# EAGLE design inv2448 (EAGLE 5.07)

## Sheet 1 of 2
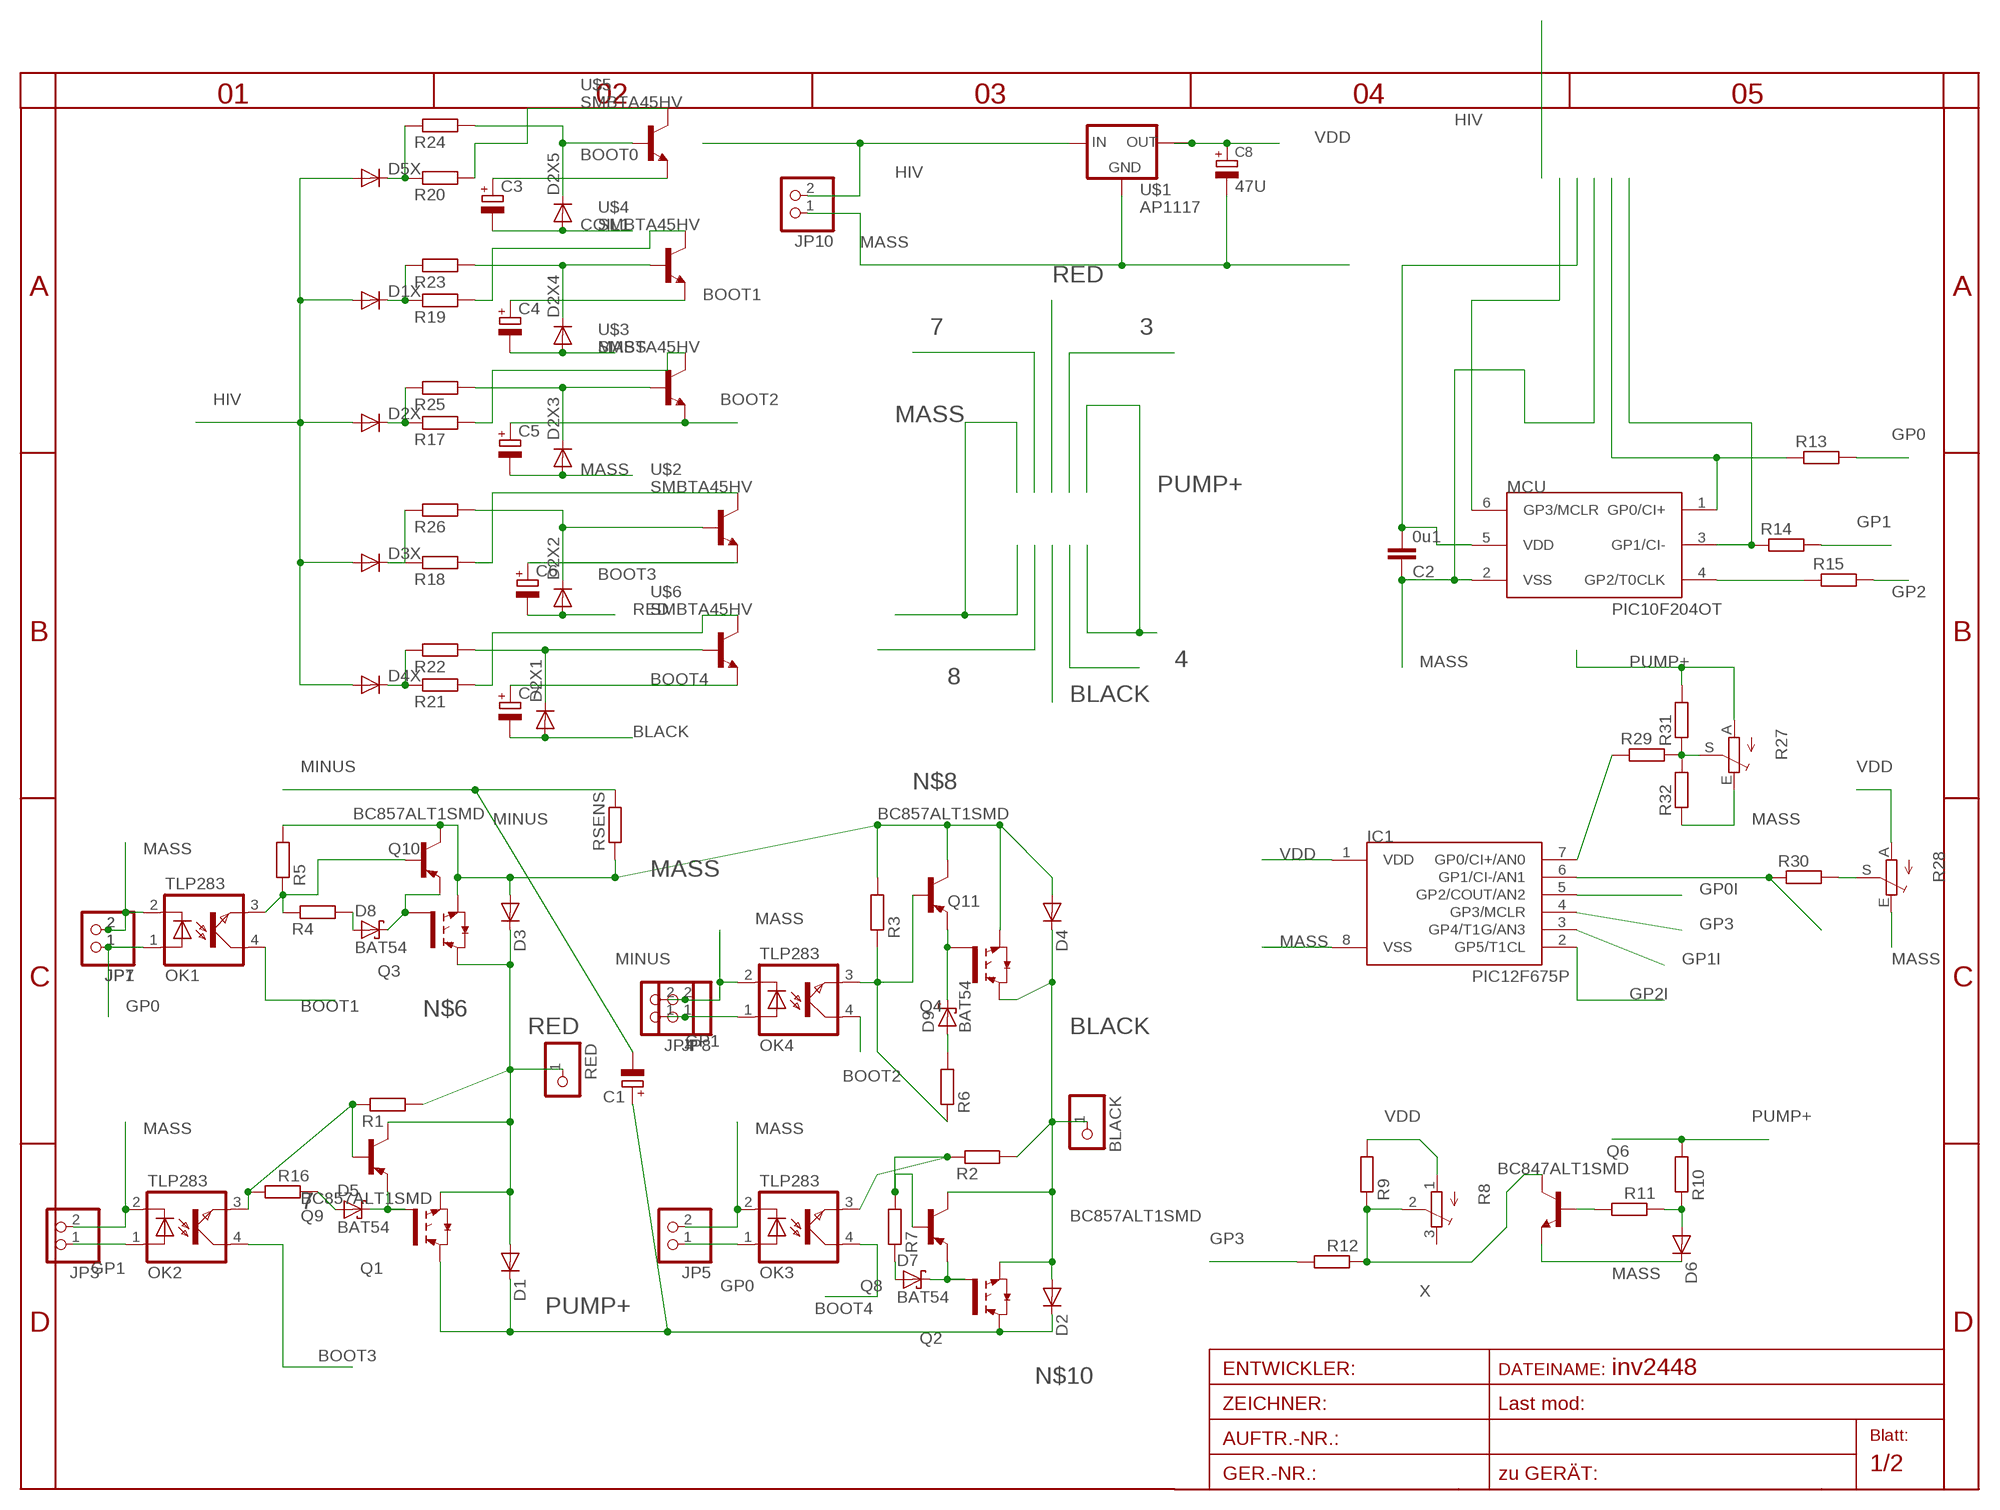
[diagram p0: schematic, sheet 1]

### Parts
BLACK  PINHD-1X14.5MM  [1X4MM5]
C1  CPOL-EUE5-13  [E5-13]
C2  0u1  C-EUC0805  [C0805]
C3  CPOL-EUC  [PANASONIC_C]
C4  CPOL-EUC  [PANASONIC_C]
C5  CPOL-EUC  [PANASONIC_C]
C6  CPOL-EUC  [PANASONIC_C]
C7  CPOL-EUC  [PANASONIC_C]
C8  47U  CPOL-EUC  [PANASONIC_C]
D1  DIODE-SMC  [SMC]
D1X  DIODE-SMA-DO214  [SMA-DO214AC]
D2  DIODE-SMC  [SMC]
D2X  DIODE-SMA-DO214  [SMA-DO214AC]
D2X1  DIODE-MINIMELF  [MINIMELF]
D2X2  DIODE-MINIMELF  [MINIMELF]
D2X3  DIODE-MINIMELF  [MINIMELF]
D2X4  DIODE-MINIMELF  [MINIMELF]
D2X5  DIODE-MINIMELF  [MINIMELF]
D3  DIODE-SMC  [SMC]
D3X  DIODE-SMA-DO214  [SMA-DO214AC]
D4  DIODE-SMC  [SMC]
D4X  DIODE-SMA-DO214  [SMA-DO214AC]
D5  BAT54  [SOT23]
D5X  DIODE-SMA-DO214  [SMA-DO214AC]
D6  DIODE-MINIMELF  [MINIMELF]
D7  BAT54  [SOT23]
D8  BAT54  [SOT23]
D9  BAT54  [SOT23]
IC1  PIC12F675P  [DIL8]
JP1  PINHD-1X2STR  [1X02]
JP3  PINHD-1X2STR  [1X02]
JP4  PINHD-1X2STR  [1X02]
JP5  PINHD-1X2STR  [1X02]
JP7  PINHD-1X2STR  [1X02]
JP8  PINHD-1X2STR  [1X02]
JP10  PINHD-1X2STR  [1X02]
MCU  PIC10F204OT  [SOT23-6]
OK1  TLP283  [MINI-FLAT-4]
OK2  TLP283  [MINI-FLAT-4]
OK3  TLP283  [MINI-FLAT-4]
OK4  TLP283  [MINI-FLAT-4]
Q1  IRG4BC15UD-S  [D2PACK]
Q2  IRG4BC15UD-S  [D2PACK]
Q3  IRG4BC15UD-S  [D2PACK]
Q4  IRG4BC15UD-S  [D2PACK]
Q6  BC847ALT1SMD  [SOT23]
Q8  BC857ALT1SMD  [SOT23-BEC]
Q9  BC857ALT1SMD  [SOT23-BEC]
Q10  BC857ALT1SMD  [SOT23-BEC]
Q11  BC857ALT1SMD  [SOT23-BEC]
R1  R-EU_R1206  [R1206]
R2  R-EU_R1206  [R1206]
R3  R-EU_R1206  [R1206]
R4  R-EU_R1206  [R1206]
R5  R-EU_R1206  [R1206]
R6  R-EU_R1206  [R1206]
R7  R-EU_R1206  [R1206]
R8  TRIM_EU-3223W  [3223W]
R9  R-EU_R1206  [R1206]
R10  R-EU_R1206  [R1206]
R11  R-EU_R1206  [R1206]
R12  R-EU_0204/7  [0204/7]
R13  R-EU_R0805  [R0805]
R14  R-EU_0207/10  [0207/10]
R15  R-EU_0207/20  [0207/20]
R16  R-EU_R1206  [R1206]
R17  R-EU_R1206  [R1206]
R18  R-EU_R1206  [R1206]
R19  R-EU_R1206  [R1206]
R20  R-EU_R1206  [R1206]
R21  R-EU_R1206  [R1206]
R22  R-EU_R1206  [R1206]
R23  R-EU_R1206  [R1206]
R24  R-EU_R1206  [R1206]
R25  R-EU_R1206  [R1206]
R26  R-EU_R1206  [R1206]
R27  TRIM_EU-RAND160  [RANDL]
R28  TRIM_EU-RAND160  [RANDL]
R29  R-EU_0207/30  [0207/30]
R30  R-EU_R0805  [R0805]
R31  R-EU_0207/30  [0207/30]
R32  R-EU_R0805  [R0805]
RED  PINHD-1X14.5MM  [1X4MM5]
RSENS  R-EU_CERAM50  [CERAM50]
U$1  AP1117  [SOT223]
U$2  SMBTA45HV  [SOT23HV]
U$3  SMBTA45HV  [SOT23HV]
U$4  SMBTA45HV  [SOT23HV]
U$5  SMBTA45HV  [SOT23HV]
U$6  SMBTA45HV  [SOT23HV]

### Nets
3: OK1.3(EMIT) Q10.B R4.1 R5.1
4: OK3.3(EMIT) Q8.B R2.1 R7.2
7: OK2.3(EMIT) Q9.B R1.1 R16.2
BLACK: BLACK.1 C7.- D2.A D2X1.A D4.C Q2.3(E) Q4.2(C) Q8.C R2.2
BOOT0: C3.+ U$5.2(E) ; also sheet 2
BOOT1: C4.+ OK1.4(COL) U$4.2(E)
BOOT2: C5.+ OK4.4(COL) U$3.2(E)
BOOT3: C6.+ OK2.4(COL) U$2.2(E)
BOOT4: C7.+ OK3.4(COL) U$6.2(E)
COIL1: C3.- D2X5.A ; also sheet 2
GP0: JP1.1 JP5.1 JP7.1 OK1.1(A) OK3.1(A) R13.2
GP0I: IC1.5(GP2/COUT/AN2) MCU.1(GP0/CI+) R13.1
GP1: JP3.1 JP4.1 JP8.1 OK2.1(A) OK4.1(A) R14.2
GP1I: IC1.3(GP4/T1G/AN3) MCU.3(GP1/CI-) R14.1
GP2: R15.2 ; also sheet 2
GP2I: IC1.2(GP5/T1CL) MCU.4(GP2/T0CLK) R15.1
GP3: IC1.4(GP3/MCLR) MCU.6(GP3/MCLR) R12.2
HIV: D1X.A D2X.A D3X.A D4X.A D5X.A JP10.2 U$1.3(IN) ; also sheet 2
MASS: C2.1 C4.- C5.- C8.- D2X3.A D2X4.A D3.A D4.A D6.C IC1.8(VSS) JP1.2 JP3.2 JP4.2 JP5.2 JP7.2 JP8.2 JP10.1 MCU.2(VSS) OK1.2(C) OK2.2(C) OK3.2(C) OK4.2(C) Q3.3(E) Q4.3(E) Q6.2(E) Q10.C Q11.C R3.2 R5.2 R27.E R28.E R32.1 RSENS.1 U$1.1(GND) ; also sheet 2
MINUS: C1.- RSENS.2 ; also sheet 2
N$2: D8.1(A) R4.2
N$4: D6.A R10.1 R11.1
N$5: Q6.1(B) R11.2
N$6: D8.3(C) Q3.1(G) Q10.E
N$7: D9.3(C) Q4.1(G) Q11.E
N$8: OK4.3(EMIT) Q11.B R3.1 R6.1
N$9: D9.1(A) R6.2
N$10: D7.3(C) Q2.1(G) Q8.E
N$11: D7.1(A) R7.1
N$12: D5.1(A) R16.1
N$13: D3X.K(C) R18.1 R26.1
N$14: D5.3(C) Q1.1(G) Q9.E
N$15: D4X.K(C) R21.1 R22.1
N$16: D2X.K(C) R17.1 R25.1
N$17: D1X.K(C) R19.1 R23.1
N$18: D5X.K(C) R20.1 R24.1
N$19: D2X1.C R22.2 U$6.1(B)
N$20: D2X5.C R24.2 U$5.1(B)
N$21: D2X4.C R23.2 U$4.1(B)
N$22: D2X2.C R26.2 U$2.1(B)
N$23: D2X3.C R25.2 U$3.1(B)
N$24: R28.S R30.2
N$25: R18.2 U$2.3(C)
N$26: R21.2 U$6.3(C)
N$27: R17.2 U$3.3(C)
N$28: R20.2 U$5.3(C)
N$29: R19.2 U$4.3(C)
N$31: IC1.6(GP1/CI-/AN1) R30.1
N$34: R27.S R29.2 R31.1 R32.2
N$35: IC1.7(GP0/CI+/AN0) R29.1
PUMP+: C1.+ D1.C D2.C Q1.2(C) Q2.2(C) R10.2 R27.A R31.2 ; also sheet 2
RED: C6.- D1.A D2X2.A D3.C Q1.3(E) Q3.2(C) Q9.C R1.2 RED.1
VDD: C2.2 C8.+ IC1.1(VDD) MCU.5(VDD) R8.1(A) R9.2 R28.A U$1.2(OUT) U$1.4(TAB)
X: Q6.3(C) R8.2(S) R9.1 R12.1
Unconnected: R8.3(E)

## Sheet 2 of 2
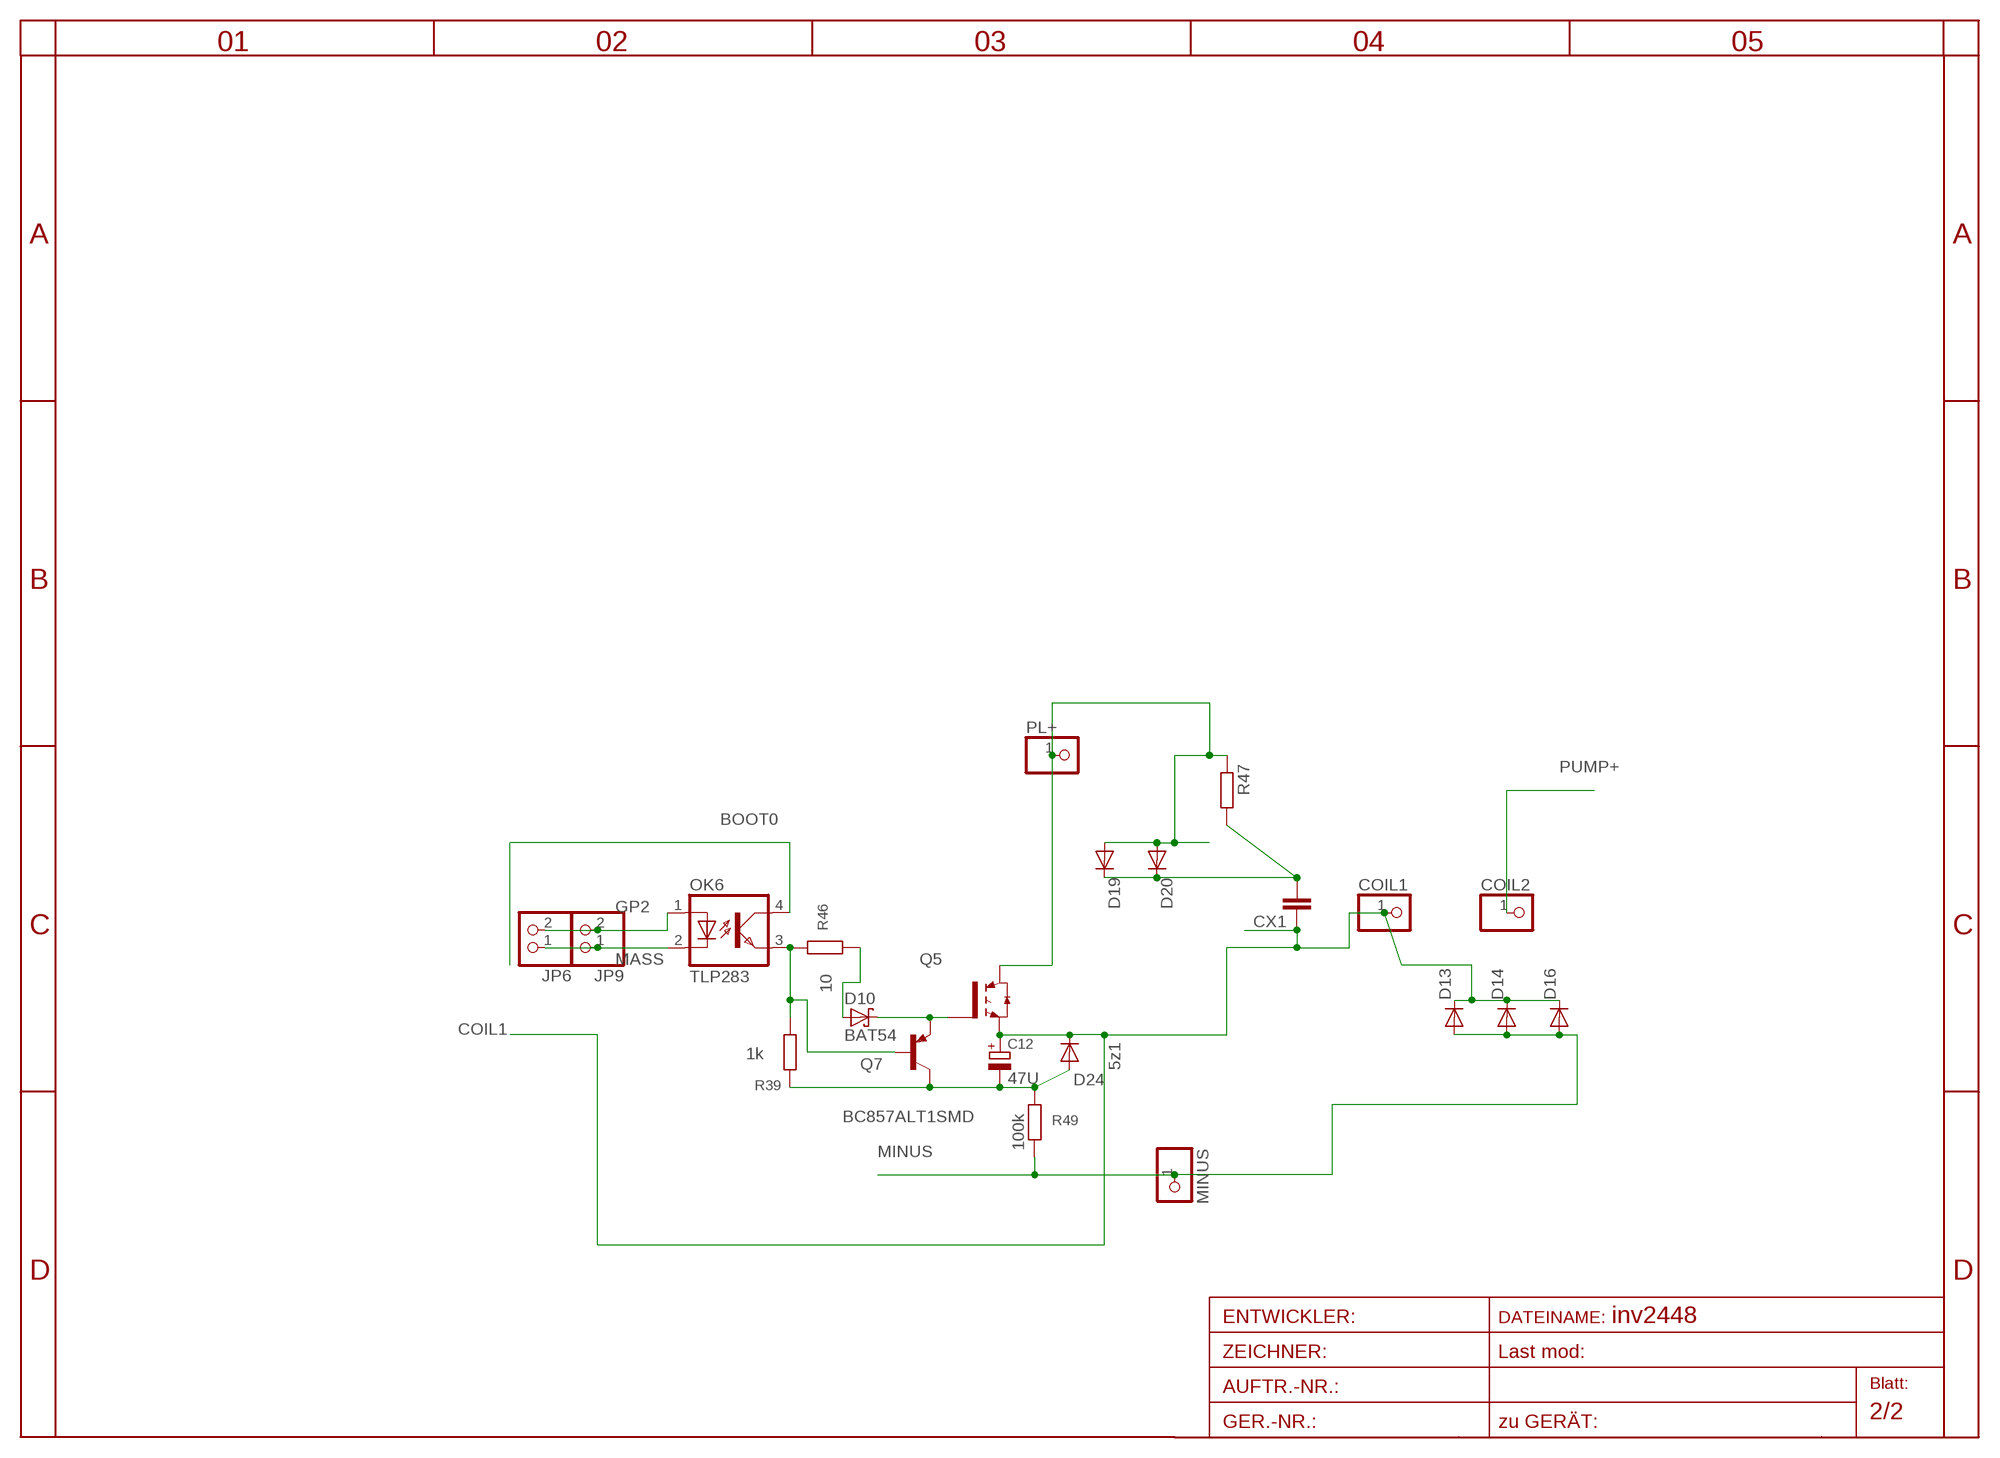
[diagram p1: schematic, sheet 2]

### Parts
C12  47U  CPOL-EUC  [PANASONIC_C]
COIL1  PINHD-1X14.5MM  [1X4MM5]
COIL2  PINHD-1X14.5MM  [1X4MM5]
CX1  CXXC22B10  [XC22B10]
D10  BAT54  [SOT23]
D13  DIODE-SMC  [SMC]
D14  DIODE-SMC  [SMC]
D16  DIODE-SMC  [SMC]
D19  DIODE-SMC  [SMC]
D20  DIODE-SMC  [SMC]
D24  5z1  DIODE-MINIMELF  [MINIMELF]
JP6  PINHD-1X2STR  [1X02]
JP9  PINHD-1X2STR  [1X02]
MINUS  PINHD-1X14.5MM  [1X4MM5]
OK6  TLP283  [MINI-FLAT-4]
PL+  PINHD-1X14.5MM  [1X4MM5]
Q5  IRG4BC15UD-S  [D2PACK]
Q7  BC857ALT1SMD  [SOT23-BEC]
R39  1k  R-EU_R1206  [R1206]
R46  10  R-EU_R1206  [R1206]
R47  R-EU_0207/5V  [0207/5V]
R49  100k  R-EU_R1206  [R1206]

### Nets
BATT-: C12.- D24.A Q7.C R39.1 R49.2
BOOT0: OK6.4(COL) ; also sheet 1
COIL1: C12.+ COIL1.1 CX1.1 D13.C D14.C D16.C D24.C Q5.3(E) ; also sheet 1
GP2: JP6.2 JP9.2 OK6.1(A) ; also sheet 1
HIV: D19.A D20.A PL+.1 Q5.2(C) R47.1 ; also sheet 1
MASS: JP6.1 JP9.1 OK6.2(C) ; also sheet 1
MINUS: D13.A D14.A D16.A MINUS.1 R49.1 ; also sheet 1
N$1: D10.3(C) Q5.1(G) Q7.E
N$3: D10.1(A) R46.1
N$43: OK6.3(EMIT) Q7.B R39.2 R46.2
PUMP+: COIL2.1 ; also sheet 1
SNUB: CX1.2 D19.C D20.C R47.2

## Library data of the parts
BLACK COIL1 COIL2 MINUS PL+ RED = pinhead:PINHD-1X1: PIN HEADER
C1 C3-C7 = rcl:CPOL-EU: POLARIZED CAPACITOR, European symbol
C2 = rcl:C-EU: CAPACITOR, European symbol
C8 C12 = rcl-2:CPOL-EU: POLARIZED CAPACITOR, European symbol
CX1 = rcl:CX: X CAPACITOR
D1 D1X D2 D2X D2X1-D2X5 D3 D3X D4 D4X D5X D6 D13 D14 D16 D19 D20 D24 = diode:DIODE-: DIODE
D5 D7-D10 = diode:BAT54: Schottky Diodes
IC1 = microchip-5:PIC12F6*: uPC nW 1k Program Flash memory 2x Timer Comparator 10b A/D converter/ 4xIN
JP1 JP3-JP10 = pinhead:PINHD-1X2: PIN HEADER
MCU = microchip-3:PIC10F2*: uPC nW 0,25/0,5k Program Flash memory Comparator
OK1-OK4 OK6 = optocoupler:TLP283: TOSHIBA PHOTOCOUPLER GaAs IRED & PHOTO-TRANSISTOR Source: http://www.semicon.toshiba.co.jp/td/en/Opto/Photocoupler/en_20050928_TLP283_datasheet.pdf
Q1-Q5 = transistor-power:IRG4BC15UD-: INSULATED GATE BIPOLAR TRANSISTOR WITH ULTRAFAST SOFT RECOVERY DIODE
Q6 = transistor-npn:BC847*: NPN Transistor
Q7-Q11 = transistor-pnp:BC857*: PNP Transistror
R1-R7 R9-R12 R16-R26 R47 RSENS = rcl:R-EU_: RESISTOR, European symbol
R8 R27 R28 = pot:TRIM_EU-: POTENTIOMETER
R13-R15 R29-R32 R39 R46 R49 = rcl-2:R-EU_: RESISTOR, European symbol
U$1 = v-reg:AP1117
U$2-U$6 = transistor-npn:SMBTA45

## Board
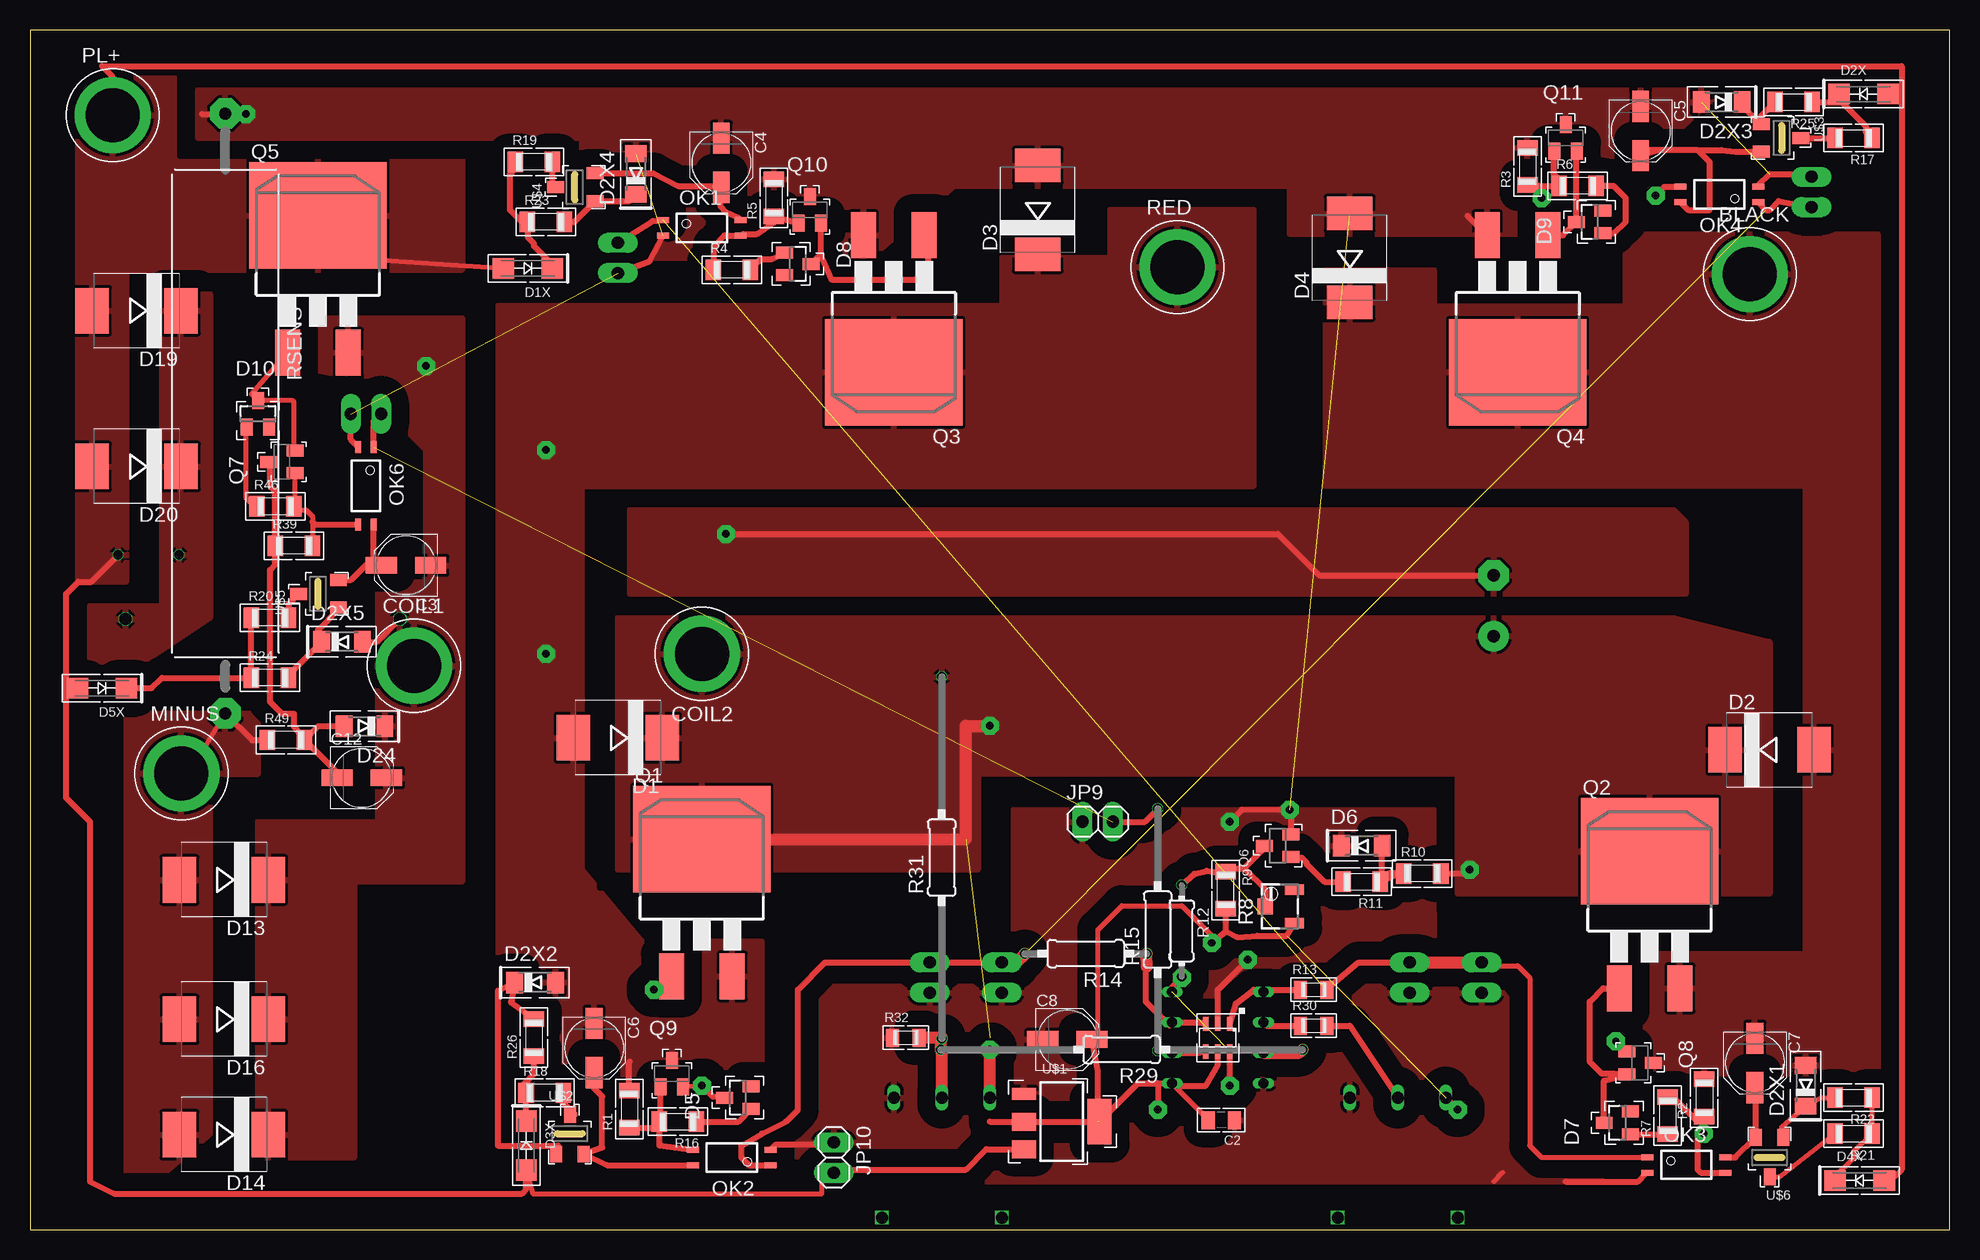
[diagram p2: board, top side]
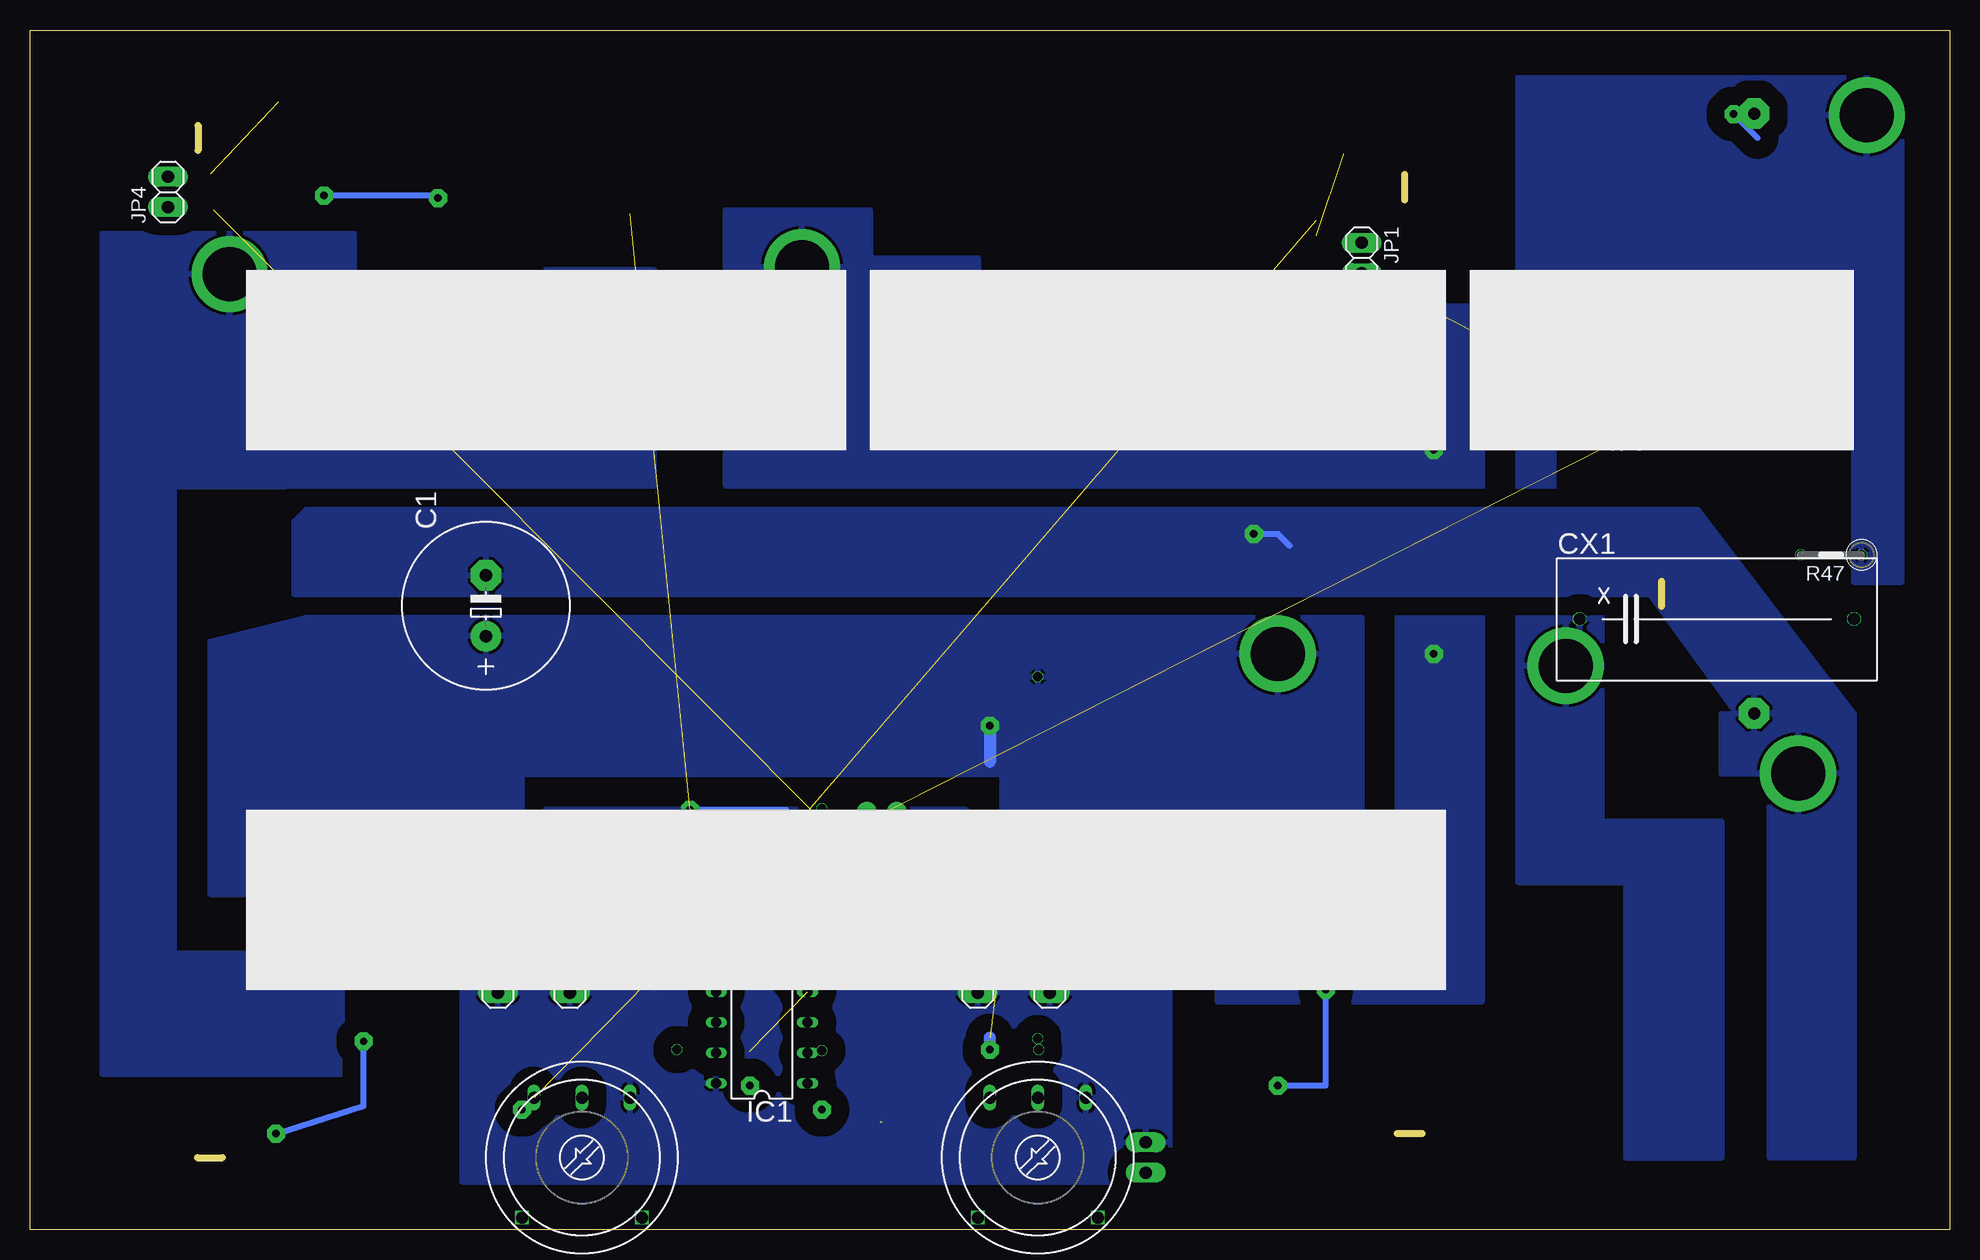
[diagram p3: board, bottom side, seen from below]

Size 160 x 100 mm. Coordinates in mm from the lower left corner, seen from the top.
Outline: 0,0 160,0 160,100 0,100 0,0
Copper layers (1*16): Top 0.035mm / dielectric 1.5mm / Bottom 0.035mm
Design rules "default": minimum track width 10mil, minimum drill 20mil, track to track 8mil, track to pad 8mil, pad to pad 8mil, via to via 8mil, smd to smd 8mil, copper to edge 40mil, drill to drill 8mil, minimum pad ring 1mil, minimum via ring 8mil, stop-mask expansion 4mil, vias tented up to drill 0mil, thermal gap 10mil

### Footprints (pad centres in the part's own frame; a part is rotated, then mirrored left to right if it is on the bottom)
1X4MM5 = drill 4.5 pad 6.35 round: 1 0,0
E5-13 = drill 1.016 pad 2.54 round: + -2.54,0 | drill 1.016 pad 2.54 octagon: - 2.54,0
C0805 = smd 1.1 x 1.5: 1 -1.1,0; 2 1.1,0
PANASONIC_C = smd 2.6 x 1.4: + 2.05,0; - -2.05,0
XC22B10 = drill 1.016 octagon: 1 -11.43,0.025; 2 11.43,0.025
SMC = smd 2.8 x 3.8: A 3.7,0; C -3.7,0
SMA-DO214AC = smd 1.8 x 1.7: A 2.05,-0.127; K -2.05,-0.127
MINIMELF = smd 1.4 x 1.8: A 1.7,0; C -1.7,0
SOT23 = smd 1 x 1.4: 1 -0.95,-1.1; 2 0.95,-1.1; 3 0,1.1
DIL8 = drill 0.8 long: 1 -3.81,-3.81; 2 -1.27,-3.81; 3 1.27,-3.81; 4 3.81,-3.81; 5 3.81,3.81; 6 1.27,3.81; 7 -1.27,3.81; 8 -3.81,3.81
1X02 = drill 1.016 pad 1.676 long: 1 -1.27,0; 2 1.27,0
SOT23-6 = smd 0.45 x 1.2: 1 -1.016,-1.15; 2 0,-1.15; 3 1.016,-1.15; 4 1.016,1.15; 5 0,1.15; 6 -1.016,1.15
MINI-FLAT-4 = smd 1 x 0.5: 1 -3.24,0.635; 2 -3.24,-0.635; 3 3.24,-0.635; 4 3.24,0.635
D2PACK = smd 2.083 x 3.81: 1 -2.54,-8.89; 3 2.54,-8.89 | smd 11.43 x 8.89: 2 0,2.54
SOT23-BEC = smd 1 x 1.4: B -0.95,-1.1; C 0,1.1; E 0.95,-1.1
R1206 = smd 1.3 x 1.7: 1 -1.55,0; 2 1.55,0
3223W = smd 0.9 x 1.6: 1 -1.4,-1.215; 3 1.4,-1.215 | smd 1.3 x 1.3: 2 0,1.215
0204/7 = drill 0.813 octagon: 1 -3.81,0; 2 3.81,0
R0805 = smd 1.1 x 1.5: 1 -1.1,0; 2 1.1,0
0207/10 = drill 0.813 octagon: 1 -5.08,0; 2 5.08,0
0207/20 = drill 0.813 octagon: 1 -10.08,0; 2 10.08,0
RANDL = drill 1 long: A -4,5; E 4,5; S 0,5 | drill 1 square: P$1 -5,-5; P$2 5,-5
0207/30 = drill 0.813 octagon: 1 -15.08,0; 2 15.08,0
0207/5V = drill 0.813 octagon: 1 -2.54,0; 2 2.54,0
CERAM50 = drill 1 pad 2.54 octagon: 1 -25,0; 2 25,0
SOT223 = smd 1 x 2: 1 -2.3,-3.15 | smd 1.5 x 2: 2 0,-3.15; 3 2.3,-3.15 | smd 3.8 x 2: 4 0,3.15
SOT23HV = smd 1 x 1.4: 1 -1.15,-1.7; 2 1.15,-1.7; 3 0,1.6

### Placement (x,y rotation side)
BLACK  143.35,79.64 0 top
C1  122,52 90 bottom
C2  99.3,9.12 180 top
C3  31.34,55.37 180 top
C4  57.62,88.92 270 top
C5  134.25,91.57 270 top
C6  47.02,15.13 270 top
C7  143.78,13.89 270 top
C8  86.46,15.85 0 top
C12  27.65,37.66 0 top
COIL1  32,47 0 top
COIL2  56,48 180 top
CX1  19.39,50.87 0 bottom
D1  49,41 180 top
D1X  41.5,80 180 top
D2  145,40 0 top
D2X  152.83,94.78 0 top
D2X1  148,12 90 top
D2X2  42.1,20.6 0 top
D2X3  141,94 180 top
D2X4  50.5,88 90 top
D2X5  26,49 0 top
D3  84,85 90 top
D3X  41.5,7 270 top
D4  110,81 90 top
D4X  152.51,4.22 0 top
D5  59,11 90 top
D5X  6,45 180 top
D6  111,32 0 top
D7  132.3,8.9 90 top
D8  64,80.5 270 top
D9  130,84 90 top
D10  19,68 0 top
D13  16.16,29.15 180 top
D14  16.16,7.91 180 top
D16  16.16,17.53 180 top
D19  8.88,76.59 180 top
D20  8.88,63.62 180 top
D24  27.89,41.96 180 top
IC1  99,16 90 bottom
JP1  49,81 270 bottom
JP3  75,21 270 bottom
JP4  148.5,86.5 90 bottom
JP5  121,21 270 bottom
JP6  28,68 180 bottom
JP7  115,21 270 bottom
JP8  81,21 270 bottom
JP9  89,34 0 top
JP10  67,6 270 top
MCU  99,16 180 top
MINUS  12.62,38.02 0 top
OK1  56,83.5 0 top
OK2  58.5,6 180 top
OK3  138.06,5.38 0 top
OK4  140.81,86.29 180 top
OK6  28,62 270 top
PL+  6.89,92.9 0 top
Q1  56,30 0 top
Q2  135,29 0 top
Q3  72,74 180 top
Q4  124,74 180 top
Q5  24,82 0 top
Q6  104,32 90 top
Q7  21,64 90 top
Q8  134.2,13.9 270 top
Q9  53.5,13 0 top
Q10  65,85 0 top
Q11  128,91 0 top
R1  49.95,10.05 90 top
R2  139.55,10.98 90 top
R3  124.83,88.62 90 top
R4  58.5,80 0 top
R5  62,86 90 top
R6  129,87 0 top
R7  136.5,9.5 90 top
R8  104.18,26.94 90 top
R9  99.67,28.3 270 top
R10  116.05,29.67 0 top
R11  111,29 180 top
R12  96,24.9 270 top
R13  107,20 0 top
R14  88,23 180 top
R15  94,25 90 top
R16  54,9 180 top
R17  152,91 180 top
R18  42.9,11.4 0 top
R19  42,89 0 top
R20  20,51 0 top
R21  152,8 180 top
R22  152,11 180 top
R23  43,84 0 top
R24  20,46 0 top
R25  147,94 180 top
R26  42,16 90 top
R27  76,6 0 bottom
R28  114,6 0 bottom
R29  91,15 180 top
R30  107,17 0 top
R31  76,31 90 top
R32  73,16 0 top
R39  22,57 0 top
R46  20.46,60.28 0 top
R47  9.88,56.24 180 bottom
R49  21.34,40.81 0 top
RED  95.65,80.23 0 top
RSENS  16.29,68.04 270 top
U$1  86,9 270 top
U$2  45,8 0 top
U$3  146,91 270 top
U$4  45.4,86.9 90 top
U$5  24,53 90 top
U$6  145,6 180 top

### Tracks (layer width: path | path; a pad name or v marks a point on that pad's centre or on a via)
3
  Top 0.5: Q10.B 62.05,84.45 R5.1 62,84 60.6,83 59.48,83 OK1.3 57.87,82.86 57,82 57,80.05 R4.1
4  (via drill 0.6 pad 1.5)
  Top 0.5: Q8.B 133.05,14.85 v132.2,15.7 | OK3.3 139.25,4.75 139,5 139,7.5 v139.5,8 139.5,9.38 R2.1 139.12,9 139,9 136.95,11.05 R7.2
  Bottom 0.5: v132.2,15.7 132.2,10.3 v139.5,8
7
  Top 0.5: R16.2 52.45,7 OK2.3 | R1.1 51.95,8.5 R16.2 | Q9.B 52.55,9.1 R16.2
BATT-
  Top 0.5: Q7.C 20,63.9 20,62 20.45,61.55 R39.1 20.45,55.45 20,55 20,44 21,43 22,43 22,41.92 R49.2 | D24.A 24.04,41.96 R49.2 | C12.- 25.6,38.1 R49.2
BLACK
  pour Top (isolate 1.5, rank 2): 108,80 117,80 117,77 133,77 133,83 154,83 154,13 134,13 134,23 148,23 148,62 108,62
  pour Bottom (isolate 1.5, rank 2): 108,80 117,80 117,77 133,77 133,83 154,83 154,13 134,13 134,23 148,23 148,62 108,62
BOOT0
  Top 0.5: 28.64,56.02 OK6.4 | 28.64,56.02 C3.+ | U$5.2 26.76,54.15 28.64,56.02
BOOT1
  Top 0.5: OK1.4 59,84.36 58,84.8 57.53,85.37 C4.+ 57.49,87 54,87 51.95,88.05 U$4.2
BOOT2
  Top 0.5: U$3.2 142.15,89.85 141,90 139,90 | 135.73,90 C5.+ | C5.+ 134.48,89.52 | OK4.4 138.22,85 140,85 140,89 139,90 | 139,90 135.73,90 | 135.73,90 134.73,90 C5.+
BOOT3
  Top 0.5: OK2.4 48.09,5.37 U$2.2 47.7,6.85 47.7,11.1 47.02,11.78 C6.+
BOOT4
  Top 0.5: OK3.4 142.16,6.01 U$6.2 143.85,11.77 C7.+
COIL1  (via drill 0.6 pad 1.5)
  Top 0.5: D2X5.A 28.93,49 CX1.1
  other vias: 33,72
  pour Top (isolate 1.5, rank 2): 22,76 36,76 36,29 27,29 27,6 19,6 19,34 29,34 29,54 33,54 33,65 27,71 22,72
  pour Bottom (isolate 1.5, rank 2): 26,76 36,76 36,29 27,29 27,6 19,6 19,34 29,34 29,54 33,54 33,65 26,72
GP0  (1 unrouted)
  Top 0.406: OK3.1 125.98,6.01 125,7 125,21 124,22 121.27,22 JP5.1
  Top 0.5: JP1.1 51.91,84.07 OK1.1 | R13.2 108,20 110.73,22.27 JP7.1
  Top 1: JP7.1 JP5.1
GP0I
  Top 0.5: MCU.1 100.52,18.82 102,20 102.62,20 IC1.5 103,20 R13.1
GP1  (1 unrouted)
  Top 0.5: 82.19,22.27 JP8.1 JP3.1 66.27,22.27 64,20 64,10 63,9 61,8 59.3,7 59.3,6 59.94,5.37 OK2.1 | JP4.1 145.73,85.73 145,85 144.71,85 OK4.1
  Top 1: 82.19,22.27 R14.2
GP1I
  Top 0.5: MCU.3 97.6,17.27 IC1.3 95,17.08 95,17 93,19 93,21.9 93.1,21.9
  Top 1: 93.1,21.9 R14.1
GP2  (1 unrouted)
  Top 0.5: OK6.1 28.64,67.36 JP6.2 | JP9.2 92.92,34 R15.2
GP2I
  Top 0.5: MCU.4 97.36,14.73 IC1.2 95.19,14.81 95,15 94.08,15 R15.1
GP3  (via drill 0.6 pad 1.5)  (1 unrouted)
  Top 0.5: MCU.6 100.02,13.98 v100,12 | R12.2 96.2,21.2 v96,21 95.19,20.19 IC1.4
HIV
  Top 0.406: 66,5 66,3 41.9,3 D3X.A | 67,5 JP10.2 | D1X.A 27.62,80.92 Q5.2
  Top 0.5: D4X.A 155.44,4.44 156,5 156,95 | 156,95 156,97 6,97 6.89,96.11 PL+.1 | 3,45 3,36 5,34 5,4 7,3 41,3 41.37,3.37 D3X.A | 3,45 3,53 4,54 5.1,54 R47.1 | U$1.3 79.7,6.7 78,5 67,5 66,5 | D5X.A 3.13,45.13 3,45 | D2X.A 155.65,94.65 156,95
  pour Top (isolate 1.5, rank 2): 4,96 36,96 36,80 8,80 8,54 4,54
  pour Bottom (isolate 1.5, rank 2): 4,96 36,96 36,80 8,80 8,54 4,54
MASS  (via drill 0.6 pad 1.5)  (4 unrouted)
  Top 0.406: 122,4 122.75,4.75
  Top 0.5: JP1.2 51.66,80.73 OK1.2 | Q4.3 119.83,84.52 | MCU.2 99,20 v101.5,22.5 | Q6.2 105.1,34.9 v105,35 101,35 v100,34 | JP10.1 65.83,7.1 62.2,7.1 OK2.2 | JP6.1 26.73,65.88 OK6.2 | OK4.2 144.05,87.05 145,88 147.73,88 JP4.2 | v18,93 14.33,93 RSENS.1 | OK3.2 134.75,4.75 134,4 128,4
  Bottom 0.5: v105,35 97,35 92,30 | v18,93 16,91
  pour Top (isolate 1.5): 14,95 141,95 128,83 105,83 105,87 77,87 70,81 52,81 48,82 48,87 46,87 46,91 14,91
  pour Top (isolate 1.5, rank 3): 82,35 117,35 117,22 121,22 131,9 131,4 64,4 64,21 74,24 82,24
  pour Bottom (isolate 1.5, rank 3): 82,35 117,35 117,22 124,22 124,4 65,4 65,21 78,21 82,24
MINUS  (via drill 0.6 pad 1.5)
  Top 0.406: RSENS.2 14.29,39.69 MINUS.1
  Top 0.5: C1.- 107.46,54.54 104,58 v58,58 | R49.1 18.52,40.81 RSENS.2
  Bottom 0.5: v58,58 56,58 55,57
  pour Top (isolate 1.5): 138,53 50,53 50,60 137,60 138,59
  pour Top (isolate 1.5, rank 3): 8,43 8,2 15,8 15,38 19,38 19,43
  pour Bottom (isolate 1.5): 8,43 21,60 60,60 60,53 25,53 17,42 9,42
  pour Bottom (isolate 1.5): 138,53 50,53 50,60 137,60 138,59
  pour Bottom (isolate 1.5, rank 3): 8,43 8,6 15,6 15,38 19,38 19,43
N$1
  Top 0.406: Q5.1 18.46,69.64 D10.3 21.9,69.1 22,69 22,65.05 Q7.E
N$2
  Top 0.5: R4.2 59.71,79.71 60.9,80.9 61.85,80.9 D8.1
N$3
  Top 0.406: R46.1 18.72,60.28 18,61 18,66.85 D10.1
N$4
  Top 0.5: R10.1 113.22,29.67 114.28,29.73 | R11.1 114.28,29.73 | D6.A 112.7,29.3 114.28,29.73
N$5
  Top 0.5: R11.2 107.9,29 106.4,30.5 106.4,30.6 106,31 105.15,31 Q6.1
N$6
  Top 0.5: 65.6,81 66,81 66.8,79.2 73.8,79.2 74.9,80.3 74.9,82.53 Q3.1 | D8.3 65.6,81 | Q10.E 65.95,81.35 65.6,81
N$7
  Top 0.5: Q4.1 127.79,82.89 D9.3 128.9,89.85 Q11.E
N$8  (via drill 0.6 pad 1.5)
  Top 0.5: Q11.B 127,89.85 127,88 127.45,87.55 R6.1 126,87 | 126,87 124.9,87 R3.1 | OK4.3 136.22,86.92 v135.5,86.2 | v126,86 126,87
  Bottom 0.5: v135.5,86.2 126.2,86.2 v126,86
N$9
  Top 0.5: D9.1 132.05,83.05 133,84 133,86 132,87 R6.2
N$10
  Top 0.5: Q2.1 131.11,20.11 130,19 130,14 131,13 132.05,13 Q8.E 131.2,12.4 D7.3
N$11
  Top 0.5: D7.1 R7.1
N$12
  Top 0.5: R16.1 59.05,9 D5.1
N$13
  Top 0.5: R26.1 42,13 41,12 41,11.75 R18.1 41.37,11.38 D3X.K
N$14  (via drill 0.6 pad 1.5)
  Top 0.406: Q9.E 56.05,12 v56,12
  Top 0.5: D5.3 56.9,11.1 v56,12 | v52,20 52.35,20 Q1.1
  Bottom 0.5: v56,12 52,12 v52,20
N$15
  Top 0.406: D4X.K 150.46,4.46 152,6 152,6.55 R21.1 R22.1
N$16
  Top 0.5: R25.1 150.43,94 | 150.43,94 D2X.K | 150.43,94 151,94 153,92 153,91.55 R17.1
N$17
  Top 0.5: R19.1 40.45,88.45 40,88 40,85 41,84 R23.1 41.5,83.95 41.5,82.7 42,82.2 42,82 43.55,80.45 D1X.K
N$18
  Top 0.5: D5X.K 10.13,45.13 11,46 R24.1 R20.1
N$19
  Top 0.406: R22.2 149.3,11 D2X1.C 146,8.55 U$6.1
N$20
  Top 0.5: R24.2 21.55,46.25 D2X5.C 24,49.3 24,50 25.7,51.7 U$5.1
N$21
  Top 0.5: R23.2 45.35,84 U$4.1 49.95,85.75 D2X4.C
N$22
  Top 0.5: U$2.1 43.7,6.3 44,7 39,7 39,19.9 D2X2.C 40.1,18.95 R26.2
N$23
  Top 0.5: D2X3.C 142.7,93.75 U$3.1 144.3,92.85 R25.2
N$24
  Top 0.5: R28.S 110,17 R30.2
N$25
  Top 0.5: U$2.3 45.4,9.6 44,11 44,11.55 R18.2
N$26
  Top 0.406: U$6.3 145.85,4.4 R21.2
N$27
  Top 0.5: U$3.3 R17.2
N$28
  Top 0.5: R20.2 21.55,52.15 U$5.3
N$29
  Top 0.5: R19.2 43.55,87.15 U$4.3
N$31
  Top 0.5: IC1.6 103.08,17 R30.1
N$34
  Top 1: R27.S 76,14.92 R29.2 75.92,15.92 R31.1 76,16 R32.2
N$35
  Top 1: IC1.7 105.81,14.73 R29.1
N$43
  Top 0.406: Q7.B 22.1,60.37 R46.2 22.29,60 23,60 23.55,59.45 23.55,59 R39.2
  Top 0.5: OK6.3 23.79,58.76 23.55,59
PUMP+  (via drill 0.6 pad 1.5)  (1 unrouted)
  Top 0.5: R10.2 119.67,29.67 v120,30
  Top 1: R27.A v80,15 | Q1.2 78,32.54 78,42 v80,42
  Bottom 1: v80,15 80,16 | v80,42 80,39
  pour Top (isolate 1.5): 145,49 145,28 119,28 119,38 79,38 79,30 49,30 49,51 137,51
  pour Bottom (isolate 1.5): 145,49 145,28 119,28 119,38 79,38 79,30 49,30 49,51 137,51
RED  (via drill 0.6 pad 1.5)
  Top 0.5: R1.2 49.95,13.95 50,14
  other vias: 43,65 43,48
  pour Top (isolate 1.5, rank 2): 102,62 102,85 90,85 90,81 81,81 81,77 39,77 39,13 61,13 61,24 51,24 46,30 46,62
  pour Bottom (isolate 1.5, rank 2): 102,62 102,85 90,85 90,81 81,81 81,77 39,77 39,19 61,19 61,24 51,24 46,30 46,62
SNUB
  pour Top (isolate 1.5, rank 2): 11,78 15,78 15,51 9,47 5,47 5,52 11,52
VDD  (via drill 0.6 pad 1.5)  (2 unrouted)
  Top 0.406: C2.2 98.2,9.18 IC1.1 | v98.5,23.9 98.5,24.5 96,27 91,27 89,25 89,16.34 C8.+
  Top 0.5: MCU.5 99,13.7 98,12 95.38,12 IC1.1 94,12.19 | 80,9 U$1.2 89,9 89,13.24 C8.+ | U$1.4 92.34,12.19 94,12.19 | v119,10 R28.A | 94,12.19 v94,10 | 99.67,24.87 R9.2 | v98.5,23.9 99.67,24.87 | 99.67,24.87 100.63,24.37 102.3,24.5 104.75,24.5 R8.1
X
  Top 0.5: R8.2 102.97,28.34 101.2,30.1 | 101.2,30.1 99.92,30.1 R9.1 99.52,29.7 98.1,29.9 97.05,29.65 R12.1 | Q6.3 102.9,31.8 101.2,30.1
